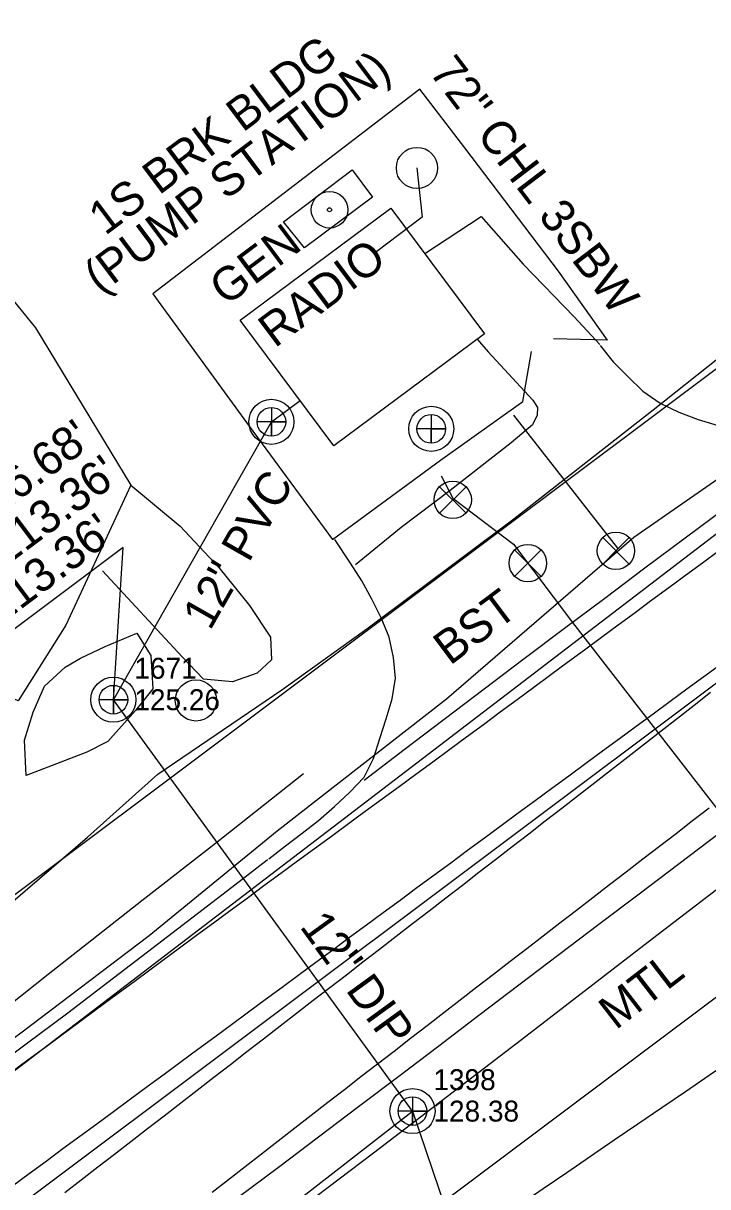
# Model space of a CAD drawing. Extents: x 2186615 to 2188822, y 629899 to 631820.
# Drawn here: x 2187392.3 to 2187474, y 630571.8 to 630710.7 of the extents above; entities that cross this region are included whole.
import ezdxf

# ---------------------------------------------------------------- set-up
doc = ezdxf.new("R2010")
doc.units = 0
for name, color, linetype in [('Exist Building', 7, 'Continuous'), ('Exist Building Text', 7, 'Continuous'), ('Exist Guardrail', 7, 'Continuous'), ('Exist Guardrail Text', 7, 'Continuous'), ('Exist Horizontal Alignment', 7, 'Continuous'), ('Exist Other Culture Area Outline', 7, 'Continuous'), ('Exist Other Culture Area Outline Text', 7, 'Continuous'), ('Exist Other Culture Fence Line', 7, 'Continuous'), ('Exist Other Culture Fence Line Text', 7, 'Continuous'), ('Exist Other Culture Gate', 7, 'Continuous'), ('Exist Other Culture Located Object CELL', 7, 'Continuous'), ('Exist Right of Way Line', 7, 'Continuous'), ('Exist Roads EOP', 7, 'Continuous'), ('Exist Roads EOP Other', 7, 'Continuous'), ('Exist Roads EOP Text', 7, 'Continuous'), ('Exist Roads EOT', 7, 'Continuous'), ('Exist Utilities Gas UG Line SUE LOS B', 7, 'Continuous'), ('Exist Utilities Other Pole CELL', 7, 'Continuous'), ('Exist Utilities Other Pole Leader', 7, 'Continuous'), ('Exist Utilities Other Pole Text', 7, 'Continuous'), ('Exist Utilities Sanitary Sewer Forced Main SUE LOS B', 7, 'Continuous'), ('Exist Utilities Sanitary Sewer Manhole CELL', 7, 'Continuous'), ('Exist Utilities Sanitary Sewer Manhole Cogo Elevation', 7, 'Continuous'), ('Exist Utilities Sanitary Sewer Manhole Cogo Number', 7, 'Continuous'), ('Exist Utilities Sanitary Sewer Manhole Leader', 7, 'Continuous'), ('Exist Utilities Sanitary Sewer UG Line', 7, 'Continuous'), ('Exist Utilities Sanitary Sewer UG Line Invert Elevation', 7, 'Continuous'), ('Exist Utilities Sanitary Sewer UG Line Text', 7, 'Continuous'), ('Exist Utilities Telephone UG FO SUE LOS B', 7, 'Continuous'), ('Exist Utilities Water UG Line SUE LOS B', 7, 'Continuous'), ('Exist Utilities Water Valve CELL', 7, 'Continuous'), ('Exist Vegetation Hedge Row', 7, 'Continuous'), ('Exist Vegetation Woods Line', 7, 'Continuous')]:
    doc.layers.add(name, color=color, linetype=linetype)

msp = doc.modelspace()

# ---------------------------------------------------------------- linework, layer by layer
at = {"layer": 'Exist Building'}
msp.add_lwpolyline([(2187447.35, 630673.63), (2187429.39, 630660.24), (2187418.2, 630675.24), (2187436.17, 630688.63)], close=True, dxfattribs=at)
at = {"layer": 'Exist Guardrail'}
for points in [[(2187600.82, 630707.03), (2187590.08, 630698.8), (2187578.34, 630689.84), (2187562.72, 630677.51), (2187547.73, 630665.68), (2187531.87, 630653.17), (2187514.82, 630639.34), (2187500.32, 630627.65), (2187485.34, 630615.46), (2187477.41, 630609.1), (2187466.89, 630601.03), (2187451.76, 630589.34), (2187434.11, 630575.84), (2187413.64, 630560.33)], [(2187241.55, 630486.35), (2187253.35, 630494.16), (2187264.21, 630501.54), (2187275.16, 630508.92), (2187284.89, 630515.72), (2187294.52, 630522.69), (2187305.63, 630530.63), (2187316.31, 630538.47), (2187330.34, 630548.74), (2187345.5, 630559.82), (2187361.87, 630571.88), (2187380.98, 630586.03), (2187387.1, 630590.71), (2187395.3, 630597.18), (2187406.46, 630605.97), (2187415.25, 630612.83), (2187425.74, 630621.13)]]:
    msp.add_lwpolyline(points, dxfattribs=at)
at = {"layer": 'Exist Horizontal Alignment'}
msp.add_line((2187136.41, 630378.11), (2188520.86, 631416.04), dxfattribs=at)
at = {"layer": 'Exist Other Culture Area Outline'}
for points in [[(2187423.37, 630686.98), (2187431.57, 630693.19), (2187434.01, 630689.91), (2187425.89, 630683.88), (2187423.37, 630686.98)], [(2187399.16, 630634.9), (2187402.09, 630636.29), (2187405.88, 630637.9), (2187407.52, 630635.21), (2187407.78, 630631.23), (2187405.7, 630628.68), (2187402.42, 630624.95), (2187399.91, 630623.7), (2187392.67, 630620.92), (2187392.47, 630625.14)], [(2187392.47, 630625.14), (2187393.49, 630628.45), (2187394.86, 630631.55), (2187397.32, 630633.83), (2187399.16, 630634.9)]]:
    msp.add_lwpolyline(points, dxfattribs=at)
at = {"layer": 'Exist Other Culture Fence Line'}
msp.add_lwpolyline([(2187462.03, 630672.85), (2187456.19, 630681.09), (2187445.01, 630695.8), (2187439.65, 630702.82), (2187407.79, 630678.39), (2187419.26, 630662.59), (2187429.21, 630649.05), (2187442.1, 630658.52), (2187451.92, 630665.54)], dxfattribs=at)
at = {"layer": 'Exist Other Culture Gate'}
for p, q in [((2187462.03, 630672.85), (2187455.59, 630673.03)), ((2187451.92, 630665.54), (2187452.96, 630671.49))]:
    msp.add_line(p, q, dxfattribs=at)
at = {"layer": 'Exist Other Culture Located Object CELL'}
for radius in [2.18, 0.24]:
    msp.add_circle((2187428.86, 630688.42), radius, dxfattribs=at)
at = {"layer": 'Exist Right of Way Line'}
for p, q in [((2187118.41, 630402.11), (2188502.83, 631440.02)), ((2187154.4, 630354.1), (2188538.85, 631392.04))]:
    msp.add_line(p, q, dxfattribs=at)
msp.add_arc((2191071.84, 625294.06), 6398.3, 123.691884, 125.65722, dxfattribs=at)
at = {"layer": 'Exist Roads EOP'}
for points in [[(2187461.17, 630672.23), (2187462.73, 630670.28), (2187464.48, 630668.51), (2187466.27, 630666.78), (2187468.31, 630665.35), (2187470.54, 630664.28), (2187472.86, 630663.4), (2187475.23, 630662.66), (2187477.64, 630662.06), (2187480.09, 630661.67), (2187482.58, 630661.66), (2187485.06, 630661.91), (2187487.53, 630662.24), (2187489.92, 630662.94), (2187492.07, 630664.22), (2187494.19, 630665.55), (2187496.29, 630666.9), (2187498.38, 630668.28), (2187500.44, 630669.69), (2187502.48, 630671.13), (2187504.52, 630672.59), (2187506.55, 630674.04), (2187508.59, 630675.49), (2187509.03, 630675.81)], [(2187432.98, 630620.36), (2187437.76, 630623.99), (2187442.54, 630627.62), (2187447.32, 630631.24), (2187452.11, 630634.86), (2187456.9, 630638.47), (2187461.7, 630642.07), (2187466.51, 630645.67), (2187471.32, 630649.25), (2187476.13, 630652.83), (2187480.94, 630656.41), (2187485.75, 630660), (2187488.95, 630662.4)], [(2187421.62, 630610.97), (2187423.6, 630612.49), (2187425.59, 630614.01), (2187427.56, 630615.54), (2187429.45, 630617.19), (2187431.27, 630618.9), (2187433, 630620.7), (2187434.12, 630622.93), (2187434.86, 630625.3), (2187435.61, 630627.68), (2187436.33, 630630.07), (2187436.72, 630632.52), (2187436.5, 630635), (2187435.96, 630637.41), (2187435.04, 630639.72), (2187433.92, 630641.94), (2187432.7, 630644.12), (2187431.38, 630646.25), (2187429.51, 630649.08)], [(2187475.35, 630614), (2187470.58, 630610.36), (2187465.81, 630606.73), (2187461.02, 630603.11), (2187456.24, 630599.49), (2187451.46, 630595.87), (2187446.67, 630592.24), (2187441.9, 630588.61), (2187437.12, 630584.98), (2187432.34, 630581.35), (2187427.55, 630577.74), (2187422.76, 630574.13), (2187417.96, 630570.53)], [(2187368.66, 630571.19), (2187373.5, 630574.74), (2187378.35, 630578.28), (2187383.18, 630581.83), (2187388, 630585.41), (2187392.82, 630588.98), (2187397.62, 630592.57), (2187402.39, 630596.22), (2187407.15, 630599.87), (2187411.91, 630603.52), (2187416.67, 630607.17), (2187421.43, 630610.82), (2187421.52, 630610.89)]]:
    msp.add_lwpolyline(points, dxfattribs=at)
at = {"layer": 'Exist Roads EOP Other'}
for points in [[(2187440.22, 630683.2), (2187446.95, 630687.63), (2187451.99, 630681.93), (2187458.05, 630675.66), (2187461.13, 630672.35)], [(2187446.47, 630672.98), (2187447.78, 630671.48), (2187453.11, 630665.7), (2187453.69, 630664.81), (2187453.64, 630663.91), (2187453.08, 630662.76), (2187450.52, 630660.6), (2187443.26, 630654.91), (2187437.42, 630650.5), (2187431.95, 630646.03)]]:
    msp.add_lwpolyline(points, dxfattribs=at)
at = {"layer": 'Exist Roads EOT'}
for points in [[(2187390.86, 630585.5), (2187392.87, 630586.98), (2187394.88, 630588.46), (2187396.9, 630589.95), (2187398.91, 630591.43), (2187400.92, 630592.92), (2187402.93, 630594.4), (2187404.94, 630595.89), (2187406.95, 630597.37), (2187408.96, 630598.86), (2187410.97, 630600.34), (2187412.99, 630601.83), (2187415, 630603.31), (2187417.01, 630604.79), (2187419.02, 630606.28), (2187421.03, 630607.76), (2187423.04, 630609.25), (2187425.06, 630610.72), (2187427.08, 630612.2), (2187429.09, 630613.68), (2187431.11, 630615.16), (2187433.13, 630616.63), (2187435.15, 630618.11), (2187437.16, 630619.59), (2187439.18, 630621.07), (2187441.19, 630622.55), (2187443.2, 630624.03), (2187445.21, 630625.52), (2187447.23, 630627), (2187449.24, 630628.49), (2187451.25, 630629.97), (2187453.26, 630631.46), (2187455.27, 630632.94), (2187457.28, 630634.43), (2187459.29, 630635.91), (2187461.3, 630637.4), (2187463.31, 630638.88), (2187465.33, 630640.37), (2187467.34, 630641.85), (2187469.35, 630643.34), (2187471.36, 630644.82), (2187473.37, 630646.3), (2187475.39, 630647.78)], [(2187391.01, 630571.93), (2187393.03, 630573.4), (2187395.04, 630574.88), (2187397.05, 630576.37), (2187399.07, 630577.85), (2187401.08, 630579.33), (2187403.09, 630580.81), (2187405.1, 630582.3), (2187407.12, 630583.78), (2187409.13, 630585.26), (2187411.14, 630586.75), (2187413.15, 630588.23), (2187415.17, 630589.71), (2187417.18, 630591.2), (2187419.19, 630592.68), (2187421.2, 630594.17), (2187423.21, 630595.65), (2187425.22, 630597.14), (2187427.23, 630598.62), (2187429.24, 630600.11), (2187431.25, 630601.59), (2187433.27, 630603.08), (2187435.28, 630604.56), (2187437.29, 630606.04), (2187439.3, 630607.53), (2187441.32, 630609.01), (2187443.33, 630610.49), (2187445.34, 630611.98), (2187447.35, 630613.46), (2187449.36, 630614.94), (2187451.38, 630616.43), (2187453.39, 630617.91), (2187455.4, 630619.4), (2187457.41, 630620.88), (2187459.43, 630622.36), (2187461.44, 630623.84), (2187463.46, 630625.32), (2187465.47, 630626.8), (2187467.49, 630628.28), (2187469.5, 630629.76), (2187471.52, 630631.24), (2187473.53, 630632.72), (2187475.55, 630634.2)], [(2187397.26, 630571.12), (2187399.24, 630572.65), (2187401.22, 630574.18), (2187403.19, 630575.71), (2187405.17, 630577.24), (2187407.15, 630578.77), (2187409.12, 630580.3), (2187411.1, 630581.83), (2187413.08, 630583.36), (2187415.05, 630584.89), (2187417.03, 630586.42), (2187419.01, 630587.95), (2187420.99, 630589.48), (2187422.96, 630591.01), (2187424.94, 630592.54), (2187426.92, 630594.07), (2187428.9, 630595.6), (2187430.87, 630597.13), (2187432.85, 630598.66), (2187434.83, 630600.19), (2187436.8, 630601.72), (2187438.78, 630603.24), (2187440.76, 630604.77), (2187442.74, 630606.3), (2187444.72, 630607.83), (2187446.69, 630609.36), (2187448.67, 630610.89), (2187450.65, 630612.42), (2187452.63, 630613.95), (2187454.6, 630615.48), (2187456.58, 630617.01), (2187458.56, 630618.54), (2187460.53, 630620.07), (2187462.51, 630621.61), (2187464.48, 630623.14), (2187466.45, 630624.68), (2187468.42, 630626.22), (2187470.39, 630627.76), (2187472.36, 630629.29), (2187474.33, 630630.83)], [(2187474.17, 630617.01), (2187472.19, 630615.48), (2187470.21, 630613.95), (2187468.23, 630612.43), (2187466.25, 630610.9), (2187464.27, 630609.37), (2187462.28, 630607.85), (2187460.3, 630606.32), (2187458.32, 630604.8), (2187456.34, 630603.27), (2187454.36, 630601.74), (2187452.39, 630600.22), (2187450.41, 630598.69), (2187448.43, 630597.16), (2187446.45, 630595.63), (2187444.47, 630594.1), (2187442.5, 630592.57), (2187440.52, 630591.04), (2187438.54, 630589.51), (2187436.56, 630587.98), (2187434.59, 630586.45), (2187432.61, 630584.92), (2187430.63, 630583.4), (2187428.65, 630581.86), (2187426.68, 630580.33), (2187424.71, 630578.8), (2187422.73, 630577.26), (2187420.76, 630575.72), (2187418.79, 630574.19), (2187416.81, 630572.66), (2187414.84, 630571.12)]]:
    msp.add_lwpolyline(points, dxfattribs=at)
at = {"layer": 'Exist Utilities Gas UG Line SUE LOS B'}
msp.add_lwpolyline([(2187331.5, 630558.33), (2187350.48, 630574.64), (2187366.06, 630585.39), (2187385.35, 630600.96), (2187399.96, 630613.56), (2187408.38, 630621.06), (2187423.17, 630631.14), (2187433.3, 630638.42), (2187450.84, 630651.54), (2187467.47, 630664.54), (2187481.97, 630676.06), (2187497.43, 630684.47), (2187517.99, 630697.1), (2187529.05, 630704.83), (2187544.97, 630716.05), (2187560.92, 630725.86), (2187575.93, 630736.98)], dxfattribs=at)
at = {"layer": 'Exist Utilities Other Pole CELL'}
for centre in [(2187439.3, 630693.41), (2187412.92, 630629.86)]:
    msp.add_circle(centre, 2.46, dxfattribs=at)
at = {"layer": 'Exist Utilities Other Pole Leader'}
msp.add_lwpolyline([(2187439.3, 630693.41), (2187439.92, 630687.54), (2187434.49, 630683.46)], dxfattribs=at)
at = {"layer": 'Exist Utilities Sanitary Sewer Forced Main SUE LOS B'}
msp.add_lwpolyline([(2187442.18, 630656.68), (2187443.57, 630654.02), (2187450.8, 630648.53), (2187457.87, 630639.18), (2187476.15, 630615.58), (2187480.17, 630611.22), (2187493.05, 630621.78), (2187508.78, 630634.21), (2187523.23, 630645.86), (2187552.85, 630669.64), (2187578.51, 630689.58), (2187603.2, 630710), (2187618.89, 630721.49), (2187639.4, 630737.18), (2187658.16, 630751.34)], dxfattribs=at)
at = {"layer": 'Exist Utilities Sanitary Sewer Manhole CELL'}
for points in [[(2187421.93, 630664.82), (2187421.93, 630661.4), (2187421.93, 630663.11), (2187423.64, 630663.11), (2187420.22, 630663.11)], [(2187441, 630664), (2187441, 630660.57), (2187441, 630662.28), (2187442.71, 630662.28), (2187439.29, 630662.28)], [(2187403.07, 630631.67), (2187403.07, 630628.24), (2187403.07, 630629.95), (2187404.78, 630629.95), (2187401.36, 630629.95)], [(2187438.76, 630582.56), (2187438.76, 630579.14), (2187438.76, 630580.85), (2187440.47, 630580.85), (2187437.05, 630580.85)]]:
    msp.add_lwpolyline(points, dxfattribs=at)
for centre, radius in [((2187421.93, 630663.11), 2.69), ((2187421.93, 630663.11), 1.71), ((2187441, 630662.28), 2.69), ((2187441, 630662.28), 1.71), ((2187403.07, 630629.95), 2.69), ((2187403.07, 630629.95), 1.71), ((2187438.76, 630580.85), 2.69), ((2187438.76, 630580.85), 1.71)]:
    msp.add_circle(centre, radius, dxfattribs=at)
at = {"layer": 'Exist Utilities Sanitary Sewer Manhole Leader'}
for points in [[(2187403.07, 630629.95), (2187404.22, 630648.11), (2187370.73, 630623.01)], [(2187438.76, 630580.85), (2187452.19, 630541.18), (2187447.79, 630537.88)]]:
    msp.add_lwpolyline(points, dxfattribs=at)
at = {"layer": 'Exist Utilities Sanitary Sewer UG Line'}
for p, q in [((2187421.93, 630663.11), (2187425.34, 630665.67)), ((2187403.07, 630629.95), (2187421.93, 630663.11)), ((2187438.76, 630580.85), (2187403.07, 630629.95)), ((2187280.26, 630457.75), (2187438.76, 630580.85))]:
    msp.add_line(p, q, dxfattribs=at)
at = {"layer": 'Exist Utilities Telephone UG FO SUE LOS B'}
msp.add_lwpolyline([(2187221.79, 630477.44), (2187244.49, 630488.55), (2187260.77, 630497.3), (2187273.17, 630505), (2187293.43, 630515), (2187319.92, 630532.54), (2187378.48, 630575.93), (2187483.97, 630656.58), (2187503.96, 630671.26), (2187608.06, 630745.86)], dxfattribs=at)
at = {"layer": 'Exist Utilities Water UG Line SUE LOS B'}
msp.add_line((2187450.81, 630663.92), (2187463.24, 630648.02), dxfattribs=at)
msp.add_lwpolyline([(2187356.85, 630563.99), (2187378.55, 630580.27), (2187392.02, 630590.2), (2187407.32, 630601.82), (2187422.62, 630614.3), (2187442.82, 630630.04), (2187465.16, 630649.35), (2187481.46, 630660.64), (2187503.4, 630674.82), (2187521.29, 630686.41), (2187544.6, 630702.68), (2187560.64, 630714.46), (2187571.68, 630722.27), (2187591.48, 630736.67), (2187622.28, 630760.13), (2187641.11, 630774.22), (2187678.52, 630802.38)], dxfattribs=at)
at = {"layer": 'Exist Utilities Water Valve CELL'}
for points in [[(2187445.15, 630655.37), (2187442, 630652.22), (2187443.57, 630653.8), (2187445.15, 630652.22), (2187442, 630655.37)], [(2187464.61, 630649.29), (2187461.46, 630646.14), (2187463.04, 630647.72), (2187464.61, 630646.14), (2187461.46, 630649.29)], [(2187454.1, 630647.82), (2187450.95, 630644.67), (2187452.53, 630646.25), (2187454.1, 630644.67), (2187450.95, 630647.82)]]:
    msp.add_lwpolyline(points, dxfattribs=at)
for centre in [(2187443.57, 630653.8), (2187463.04, 630647.72), (2187452.53, 630646.25)]:
    msp.add_circle(centre, 2.23, dxfattribs=at)
at = {"layer": 'Exist Vegetation Hedge Row'}
msp.add_lwpolyline([(2187405.17, 630655.55), (2187411.04, 630650.68), (2187415.64, 630645.72), (2187419.32, 630641.19), (2187421.83, 630637.43), (2187421.94, 630634.72), (2187420.24, 630633.11), (2187417.3, 630632.1), (2187413.84, 630632.39), (2187411.27, 630635.05), (2187401.78, 630645.33)], dxfattribs=at)
at = {"layer": 'Exist Vegetation Woods Line'}
msp.add_lwpolyline([(2187388.44, 630731.04), (2187398.57, 630741.59), (2187399.27, 630751.66), (2187417.94, 630748.09), (2187444.68, 630746.74), (2187452.32, 630744.96), (2187454.26, 630743.28), (2187453.1, 630740.34), (2187448.77, 630726.66), (2187441.92, 630727.41), (2187434.23, 630726.02), (2187429.19, 630724.52), (2187414.68, 630720.37), (2187404.62, 630725.21), (2187388.96, 630714.9), (2187379.73, 630703.48), (2187385.48, 630684.53), (2187393.76, 630674.34), (2187405.17, 630655.55), (2187397.38, 630638.84), (2187391.69, 630629.83), (2187375.44, 630637.31), (2187372.39, 630634.21)], dxfattribs=at)

# ---------------------------------------------------------------- texts
at = {"layer": 'Exist Building Text'}
for s, p in [('1S BRK BLDG', (2187402.09, 630685.28)), ('(PUMP STATION)', (2187401.51, 630678.29))]:
    msp.add_text(s, height=4, rotation=36.8593, dxfattribs=at).set_placement(p)
at = {"layer": 'Exist Guardrail Text'}
msp.add_text('MTL', height=4, rotation=37.6984, dxfattribs=at).set_placement((2187463.02, 630590.46))
at = {"layer": 'Exist Other Culture Area Outline Text'}
msp.add_text('GEN', height=4, rotation=36.8593, dxfattribs=at).set_placement((2187416.51, 630676.86))
at = {"layer": 'Exist Other Culture Fence Line Text'}
msp.add_text('72" CHL 3SBW', height=4, rotation=307.2412, dxfattribs=at).set_placement((2187440.65, 630704.84))
at = {"layer": 'Exist Roads EOP Text'}
msp.add_text('BST', height=4, rotation=36.8593, dxfattribs=at).set_placement((2187443.23, 630633.97))
at = {"layer": 'Exist Utilities Other Pole Text'}
msp.add_text('RADIO', height=4, rotation=36.8593, dxfattribs=at).set_placement((2187422.34, 630671.85))
at = {"layer": 'Exist Utilities Sanitary Sewer Manhole Cogo Elevation'}
for s, p in [('125.26', (2187405.57, 630628.7)), ('128.38', (2187441.26, 630579.6))]:
    msp.add_text(s, height=2.5, dxfattribs=at).set_placement(p)
at = {"layer": 'Exist Utilities Sanitary Sewer Manhole Cogo Number'}
for s, p in [('1671', (2187405.57, 630632.45)), ('1398', (2187441.26, 630583.35))]:
    msp.add_text(s, height=2.5, dxfattribs=at).set_placement(p)
at = {"layer": 'Exist Utilities Sanitary Sewer UG Line Invert Elevation'}
for s, p in [("INV IN(SE)=116.68'", (2187363.18, 630632.27)), ("INV IN(SE)=113.36'", (2187366.48, 630628.03)), ("INV OUT=113.36'", (2187369.67, 630623.94))]:
    msp.add_text(s, height=4, rotation=36.8593, dxfattribs=at).set_placement(p)
at = {"layer": 'Exist Utilities Sanitary Sewer UG Line Text'}
for s, rotation, p in [('12" PVC', 60.3639, (2187414.61, 630638.1)), ('12" DIP', 306.0111, (2187425.22, 630602.86))]:
    msp.add_text(s, height=4, rotation=rotation, dxfattribs=at).set_placement(p)

doc.saveas('drawing.dxf')
